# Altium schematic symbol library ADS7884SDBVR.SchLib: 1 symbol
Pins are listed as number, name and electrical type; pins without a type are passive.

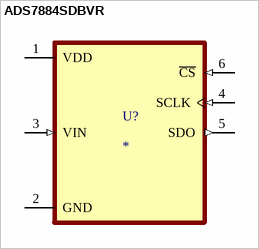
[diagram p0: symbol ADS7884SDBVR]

## ADS7884SDBVR
designator U?
2.7V-5.5V, 10 Bit, 3MSPS, Serial ADC 6-SOT-23 -40 to 125; MF: Texas Instruments; MP: ADS7884SDBVR
footprint ADS7884SDBVR
pins: 1 VDD (power), 2 GND (power), 3 VIN (in), 4 SCLK (in), 5 SDO (out), 6 ~{CS} (in)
